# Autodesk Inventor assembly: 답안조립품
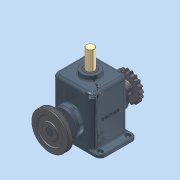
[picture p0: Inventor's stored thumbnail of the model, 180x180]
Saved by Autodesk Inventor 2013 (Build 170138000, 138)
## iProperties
Created: 2015-03
Part Number: 답안조립품
Document SubType Name: Assembly
Designer: Administrator
Author: Administrator
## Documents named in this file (15)
- C:\Documents and Settings\Administrator\바탕 화면\350305V1030\답안조립품.iam
- C:\Documents and Settings\Administrator\바탕 화면\350305V1030\본체.ipt
- C:\Documents and Settings\Administrator\바탕 화면\350305V1030\베어링 6205.ipt
- C:\Documents and Settings\Administrator\바탕 화면\350305V1030\커버.ipt
- C:\Documents and Settings\Administrator\바탕 화면\350305V1030\M4x0.5.ipt
- C:\Documents and Settings\Administrator\바탕 화면\350305V1030\편심축.ipt
- C:\Documents and Settings\Administrator\바탕 화면\350305V1030\오일실.ipt
- C:\Documents and Settings\Administrator\바탕 화면\350305V1030\키 8x8.ipt
- C:\Documents and Settings\Administrator\바탕 화면\350305V1030\체인 스프로킷.ipt
- C:\Documents and Settings\Administrator\바탕 화면\350305V1030\멈춤나사 M5x0.5.ipt
- C:\Documents and Settings\Administrator\바탕 화면\350305V1030\V-벨트풀리.ipt
- C:\Documents and Settings\Administrator\바탕 화면\350305V1030\멈춤링.ipt
- C:\Documents and Settings\Administrator\바탕 화면\350305V1030\부시.ipt
- C:\Documents and Settings\Administrator\바탕 화면\350305V1030\슬라이드.ipt
- C:\Documents and Settings\Administrator\바탕 화면\350305V1030\7 - 가변스프링.ipt
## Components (9 placed, 4 different names)
1. M4x0.5:1
2. M4x0.5:2
3. M4x0.5:3
4. M4x0.5:4
5. M4x0.5:5
6. M4x0.5:6
7. 5-체인 스프로킷:1 — 각도:2, 플러쉬:1
8. V-벨트풀리:1 — 각도:4, 플러쉬:2
9. 7 - 가변스프링:1
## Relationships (4: Angle 2, Flush 2)
- 각도:2 [Angle]: 5-체인 스프로킷:1
- 플러쉬:1 [Flush]: 5-체인 스프로킷:1
- 각도:4 [Angle]: V-벨트풀리:1
- 플러쉬:2 [Flush]: V-벨트풀리:1
